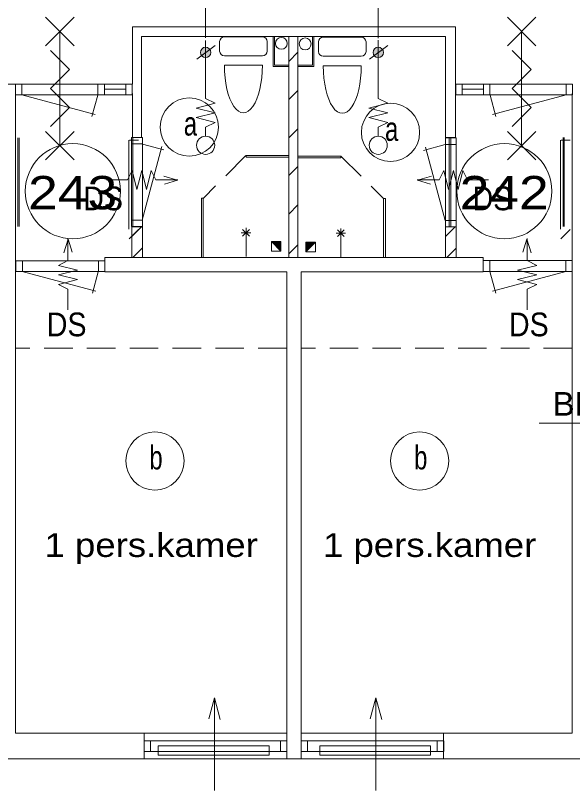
# Model space of a CAD drawing. Extents: x 295824 to 414724, y 24924 to 109024.
# Drawn here: x 320086 to 325944, y 87221 to 95369 of the extents above; entities that cross this region are included whole.
import ezdxf
from ezdxf.enums import TextEntityAlignment as Align

# ---------------------------------------------------------------- set-up
doc = ezdxf.new("R2010")
doc.units = 0
doc.header["$LTSCALE"] = 100
doc.linetypes.add('MEDIUM_DASHED', pattern=[4.5, 3, -1.5])
for name, color, linetype, lineweight in [('1', 7, 'Continuous', 13), ('16', 7, 'Continuous', 13), ('24', 7, 'Continuous', 13), ('61', 7, 'Continuous', 13)]:
    doc.layers.add(name, color=color, linetype=linetype, lineweight=lineweight)

msp = doc.modelspace()

# ---------------------------------------------------------------- hatches: boundary and pattern name
at = {"layer": '24'}
for points in [[(322140.1, 94981.2, 1), (322031.5, 94981.2, 1)], [(323955.6, 94981.2, 1), (323847, 94981.2, 1)]]:
    msp.add_hatch(color=256, dxfattribs=at).paths.add_polyline_path(points)
at = {"layer": '61'}
for points in [[(322777.9, 92991.3), (322877.9, 92891.3), (322877.9, 92991.3)], [(323240.3, 92985.9), (323140.3, 92885.9), (323140.3, 92985.9)]]:
    msp.add_hatch(color=256, dxfattribs=at).paths.add_polyline_path(points)

# ---------------------------------------------------------------- linework, layer by layer
at = {"layer": '1'}
for p, q in [((322085.8, 95135.8), (322085.8, 96018.7)), ((323901.3, 95130.8), (323901.3, 96018.7))]:
    msp.add_line(p, q, dxfattribs=at)
at = {"layer": '16'}
for p, q in [((321413.1, 93739.9), (321363.1, 93539.9)), ((324690.6, 93739.9), (324740.6, 93539.9)), ((320536.7, 92641.7), (320736.7, 92591.7)), ((325567, 92641.7), (325367, 92591.7))]:
    msp.add_line(p, q, dxfattribs=at)
at = {"layer": '24'}
for p, q in [((322085.8, 94545.8), (322085.8, 95106.6)), ((323901.3, 94545.8), (323901.3, 95108.1)), ((321994.2, 94910.4), (322185.7, 95052.1)), ((323809.7, 94910.4), (324001.2, 95052.1)), ((321788.5, 93636.5), (321644.3, 93681.5)), ((321652.7, 93594.1), (321788.5, 93636.5)), ((324315.2, 93636.5), (324459.3, 93681.5)), ((324451, 93594.1), (324315.2, 93636.5)), ((320640.1, 93017.1), (320595, 92872.9)), ((320682.5, 92881.3), (320640.1, 93017.1)), ((325421.2, 92881.3), (325463.6, 93017.1)), ((325463.6, 93017.1), (325508.6, 92872.9)), ((325591.5, 91082.6), (327952.3, 91082.6)), ((322177.4, 88195.7), (322117.8, 87973.2)), ((323876.3, 88195.7), (323816.7, 87973.2))]:
    msp.add_line(p, q, dxfattribs=at)
for points in [[(322085.8, 94095.8), (322085.8, 94195.8), (322185.8, 94245.8), (321985.8, 94295.8), (322185.8, 94345.8), (321985.8, 94395.8), (322185.8, 94445.8), (322085.8, 94495.8), (322085.8, 94545.8)], [(323901.3, 94095.8), (323901.3, 94195.8), (324001.3, 94245.8), (323801.3, 94295.8), (324001.3, 94345.8), (323801.3, 94395.8), (324001.3, 94445.8), (323901.3, 94495.8), (323901.3, 94545.8)], [(321363.1, 93539.9), (321313.1, 93739.9), (321263.1, 93639.9), (321044.4, 93639.9)], [(321794.4, 93639.9), (321563.1, 93639.9), (321513.1, 93739.9), (321463.1, 93539.9), (321413.1, 93739.9)], [(324309.3, 93639.9), (324540.6, 93639.9), (324590.6, 93739.9), (324640.6, 93539.9), (324690.6, 93739.9)], [(324740.6, 93539.9), (324790.6, 93739.9), (324840.6, 93639.9), (325059.3, 93639.9)], [(320636.7, 93023), (320636.7, 92791.7), (320536.7, 92741.7), (320736.7, 92691.7), (320536.7, 92641.7)], [(325467, 93023), (325467, 92791.7), (325567, 92741.7), (325367, 92691.7), (325567, 92641.7)], [(320736.7, 92591.7), (320536.7, 92541.7), (320636.7, 92491.7), (320636.7, 92273)], [(325367, 92591.7), (325567, 92541.7), (325467, 92491.7), (325467, 92273)], [(322177.4, 87220.7), (322177.4, 88195.7), (322239.1, 87965.5)], [(323876.3, 87220.7), (323876.3, 88195.7), (323938, 87965.5)]]:
    msp.add_lwpolyline(points, dxfattribs=at)
for points in [[(321586.1, 87691.5), (322752, 87691.5), (322752, 87591.5), (321586.1, 87591.5)], [(323285, 87691.5), (324451, 87691.5), (324451, 87591.5), (323285, 87591.5)]]:
    msp.add_lwpolyline(points, close=True, dxfattribs=at)
for centre, radius in [((322085.8, 94981.2), 54.3), ((323901.3, 94981.2), 54.3), ((322085.8, 94004.2), 95), ((323901.3, 94004.2), 95)]:
    msp.add_circle(centre, radius, dxfattribs=at)
at = {"layer": '61'}
for p, q in [((320403, 95051.1), (320703, 95351.1)), ((320703, 95051.1), (320403, 95351.1)), ((325258.8, 95051.1), (325558.8, 95351.1)), ((325558.8, 95051.1), (325258.8, 95351.1)), ((320553, 95201.1), (320553, 94001.1)), ((325408.8, 95201.1), (325408.8, 94001.1)), ((321409.7, 94086.3), (321409.7, 95148.4)), ((322232.9, 94995.4), (322232.9, 95095.4)), ((322282.9, 95145.4), (322682.9, 95145.4)), ((322732.9, 95095.4), (322732.9, 94995.4)), ((322794.7, 94833.4), (322794.7, 95148.4)), ((322809.7, 94848.4), (322809.7, 95148.4)), ((322959.7, 92823.4), (322959.7, 95148.4)), ((323056, 92823.4), (323056, 95148.4)), ((323209.8, 95147.9), (323209.8, 94847.9)), ((323322.2, 95140.5), (323722.2, 95140.5)), ((323272.2, 94990.5), (323272.2, 95090.5)), ((323772.2, 95090.5), (323772.2, 94990.5)), ((322682.9, 94945.4), (322282.9, 94945.4)), ((323055.4, 94982.4), (322959.6, 94886.7)), ((323722.2, 94940.5), (323322.2, 94940.5)), ((322959.7, 94848.4), (322809.7, 94848.4)), ((323209.8, 94847.9), (323059.8, 94847.9)), ((322282.9, 94845.4), (322682.9, 94845.4)), ((322959.7, 94833.4), (322794.7, 94833.4)), ((323322.2, 94840.5), (323722.2, 94840.5)), ((319949.3, 94648.3), (320090.5, 94648.3)), ((320153.5, 94648.3), (320153.5, 94534.3)), ((320953.5, 94648.3), (320953.5, 94534.3)), ((321020.5, 94648.3), (321020.5, 94534.3)), ((321246.5, 94648.3), (321246.5, 94534.3)), ((324714.9, 94084.9), (324714.9, 94650.7)), ((324783.1, 94648.3), (324783.1, 94534.3)), ((325009.1, 94648.3), (325009.1, 94534.3)), ((325076.1, 94648.3), (325076.1, 94534.3)), ((325876.1, 94648.3), (325876.1, 94534.3)), ((320087.1, 94548.4), (320087.1, 87823.4)), ((320152.7, 94533.7), (320925.4, 94326.6)), ((320951.1, 94533.1), (320890.3, 94306.2)), ((321246.5, 94594.2), (321020.5, 94594.2)), ((321314.9, 94086.3), (321314.9, 94548.4)), ((323055.4, 94581.5), (322959.6, 94485.8)), ((324783.1, 94594.2), (325009.1, 94594.2)), ((325078.4, 94533.1), (325139.2, 94306.2)), ((325876.9, 94533.7), (325104.1, 94326.6)), ((325940.1, 94548.4), (325940.1, 87823.4)), ((320403, 93851.1), (320703, 94151.1)), ((320703, 93851.1), (320403, 94151.1)), ((323055.4, 94178.2), (322959.6, 94082.4)), ((325258.8, 93851.1), (325558.8, 94151.1)), ((325558.8, 93851.1), (325258.8, 94151.1)), ((320110.3, 93148.9), (320110.3, 94081.3)), ((320126.1, 93148.9), (320126.1, 94081.3)), ((321278.6, 93123.7), (321278.6, 94057.7)), ((321380.8, 94058.5), (321286.1, 94058.5)), ((321307.4, 93151.5), (321307.4, 94085.5)), ((321409.7, 94086.3), (321314.9, 94086.3)), ((321318.4, 93151.5), (321318.4, 94085.5)), ((324714.9, 94084.9), (324609.7, 94084.9)), ((324648.4, 93148.9), (324648.4, 94081.3)), ((324664.2, 93148.9), (324664.2, 94081.3)), ((324720.9, 93148.9), (324720.9, 94081.3)), ((325816.7, 93123.7), (325816.7, 94057.7)), ((325918.9, 94058.5), (325824.2, 94058.5)), ((325845.5, 93151.5), (325845.5, 94085.5)), ((325856.5, 93151.5), (325856.5, 94085.5)), ((321307.4, 94018.5), (321421.4, 94018.5)), ((321419.5, 93217.8), (321626.5, 93990.5)), ((321420.1, 94016.2), (321646.9, 93955.4)), ((324603.1, 94011.9), (324376.2, 93951.2)), ((324603.7, 93213.5), (324396.6, 93986.3)), ((324720.9, 94014.3), (324606.9, 94014.3)), ((322960.8, 93897), (322511.3, 93897)), ((322511.3, 93897), (322511.3, 93879)), ((322960.4, 93879), (322511.3, 93879)), ((323057.5, 93891.6), (323506.9, 93891.6)), ((323057.8, 93873.6), (323506.9, 93873.6)), ((323506.9, 93891.6), (323506.9, 93873.6)), ((323055.4, 93782.2), (322959.6, 93686.4)), ((322060.4, 92829), (322060.4, 93449.5)), ((323957.8, 92823.6), (323957.8, 93444.1)), ((323055.4, 93377.6), (322959.6, 93281.8)), ((321307.4, 93218.5), (321421.4, 93218.5)), ((321420.8, 93151.5), (321306.8, 93151.5)), ((321420.1, 93148), (321310.1, 93148)), ((321310.1, 93148), (321310.1, 92823.9)), ((321409.8, 93146.8), (321310.1, 93047.1)), ((321420.1, 93148), (321420.1, 92823.9)), ((324720.9, 93214.3), (324606.9, 93214.3)), ((324708.3, 93146.8), (324608.6, 93047.1)), ((324719.1, 93148), (324609.1, 93148)), ((324609.1, 93148), (324609.1, 92823.9)), ((324719.1, 93148), (324719.1, 92823.9)), ((321381, 93118.9), (321281.3, 93019.2)), ((322560.3, 93085.5), (322460.3, 93085.5)), ((322545.6, 93050.1), (322474.9, 93120.8)), ((322545.6, 93120.8), (322474.9, 93050.1)), ((322510.3, 93035.5), (322510.3, 93135.5)), ((323458, 93080.1), (323558, 93080.1)), ((323472.6, 93044.8), (323543.3, 93115.5)), ((323472.6, 93115.5), (323543.3, 93044.8)), ((323508, 93030.1), (323508, 93130.1)), ((325919.1, 93118.9), (325819.4, 93019.2)), ((322510.3, 93035.5), (322510.3, 92835.5)), ((323508, 93030.1), (323508, 92830.1)), ((321418.4, 92924.2), (321318.7, 92824.5)), ((323055.4, 92959.5), (322959.6, 92863.7)), ((324720.5, 92924.2), (324620.9, 92824.5)), ((321420.1, 92823.9), (321310.1, 92823.9)), ((324719.1, 92823.9), (324609.1, 92823.9)), ((320158, 92790.9), (320158, 92676.9)), ((320958, 92790.9), (320958, 92676.9)), ((321025, 92790.9), (321025, 92676.9)), ((325005.7, 92791.9), (325005.7, 92677.9)), ((325072.7, 92791.9), (325072.7, 92677.9)), ((325872.7, 92791.9), (325872.7, 92677.9)), ((320157.3, 92676.2), (320930, 92469.2)), ((320955.7, 92675.6), (320894.9, 92448.8)), ((322940.1, 87553.4), (322940.1, 92673.4)), ((323090.1, 87553.4), (323090.1, 92673.4)), ((325075.1, 92676.7), (325135.8, 92449.8)), ((325873.5, 92677.3), (325100.7, 92470.3)), ((320087.1, 87823.4), (322940.1, 87823.4)), ((321440.7, 87552.2), (321440.7, 87822.2)), ((325940.1, 87823.4), (323090.1, 87823.4)), ((324588.7, 87552.2), (324588.7, 87822.4)), ((321507.5, 87630.5), (321507.5, 87744.3)), ((322872.5, 87629.9), (322872.5, 87743.9)), ((323156, 87630.8), (323156, 87744.8)), ((324520.3, 87630.5), (324520.3, 87744.2)), ((326233, 87553.4), (307806, 87553.4))]:
    msp.add_line(p, q, dxfattribs=at)
at = {"layer": '61', "linetype": 'MEDIUM_DASHED'}
for p, q in [((322509.2, 93896.5), (322062.4, 93449.6)), ((323509, 93891.2), (323955.9, 93444.3)), ((322937.9, 91870), (320090.8, 91870)), ((325940.1, 91870), (323091.2, 91870))]:
    msp.add_line(p, q, dxfattribs=at)
at = {"layer": '61'}
for points in [[(324714.9, 94648.4), (324714.9, 95248.4), (321314.9, 95248.4), (321314.9, 94648.4)], [(324609.7, 94084.9), (324609.7, 95148.4), (321409.7, 95148.4)], [(323224.8, 95147.9), (323224.8, 94832.9), (323059.8, 94832.9)], [(320453, 95001.1), (320653, 94801.1), (320453, 94601.1), (320653, 94401.1), (320453, 94201.1)], [(325308.8, 95001.1), (325508.8, 94801.1), (325308.8, 94601.1), (325508.8, 94401.1), (325308.8, 94201.1)], [(322042.4, 92829), (322042.4, 93449.5), (322060.4, 93449.5)], [(323975.8, 92823.6), (323975.8, 93444.1), (323957.8, 93444.1)], [(322877.9, 92891.3), (322877.9, 92991.3), (322777.9, 92991.3)], [(323140.3, 92885.9), (323140.3, 92985.9), (323240.3, 92985.9)], [(323089.9, 92673.4), (325004.9, 92673.4), (325004.9, 92823.4), (321025.5, 92823.4)], [(322939.9, 92673.4), (321025.5, 92673.4), (321025.5, 92823.4)], [(320091, 92790.9), (320091, 92676.9), (321025, 92676.9)], [(321025, 92790.9), (320091, 92790.9), (320091, 92676.9)], [(325939.7, 92791.9), (325939.7, 92677.9), (325005.7, 92677.9)], [(325005.7, 92791.9), (325939.7, 92791.9), (325939.7, 92677.9)]]:
    msp.add_lwpolyline(points, dxfattribs=at)
for points in [[(321313.5, 94648.3), (321313.5, 94534.3), (320086.5, 94534.3), (320086.5, 94648.3)], [(321313.5, 94648.3), (321313.5, 94534.3), (320086.5, 94534.3), (320086.5, 94648.3)], [(325943.1, 94648.3), (325943.1, 94534.3), (324716.7, 94534.3), (324716.7, 94648.3)], [(325943.1, 94648.3), (325943.1, 94534.3), (324716.7, 94534.3), (324716.7, 94648.3)], [(321307.4, 93151.5), (321307.4, 94085.5), (321421.4, 94085.5), (321421.4, 93151.5)], [(324720.9, 94082.2), (324606.9, 94082.2), (324606.9, 93148.2), (324720.9, 93148.2)], [(322877.9, 92891.3), (322777.9, 92891.3), (322777.9, 92991.3)], [(322777.9, 92991.3), (322877.9, 92891.3), (322877.9, 92991.3)], [(323140.3, 92885.9), (323240.3, 92885.9), (323240.3, 92985.9)], [(323240.3, 92985.9), (323140.3, 92885.9), (323140.3, 92985.9)], [(321440.6, 87630.3), (321440.6, 87744.3), (322939.3, 87744.3), (322939.3, 87630.3)], [(323089.6, 87630.5), (323089.6, 87744.5), (324589, 87744.5), (324589, 87630.5)]]:
    msp.add_lwpolyline(points, close=True, dxfattribs=at)
for centre, radius in [((322882.2, 95075.9), 62.5), ((323132.2, 95070.4), 62.5), ((321914.1, 94195.9), 306.3), ((324030, 94140.2), 306.3), ((320688.9, 93521.8), 500), ((325227, 93521.8), 500), ((321552.2, 90685.4), 306.3), ((324336.3, 90685.4), 306.3)]:
    msp.add_circle(centre, radius, dxfattribs=at)
for centre, start, end in [((322282.9, 95095.4), 90, 180), ((322682.9, 95095.4), 0, 90), ((323322.2, 95090.5), 90, 180), ((323722.2, 95090.5), 0, 90), ((322282.9, 94995.4), 180, 270), ((322682.9, 94995.4), 270, 0), ((323322.2, 94990.5), 180, 270), ((323722.2, 94990.5), 270, 0)]:
    msp.add_arc(centre, 50, start, end, dxfattribs=at)
for centre in [(322482.9, 94845.4), (323522.2, 94840.5)]:
    msp.add_ellipse(centre, major_axis=(0, -500), ratio=0.4, start_param=4.712389, end_param=7.853982, dxfattribs=at)

# ---------------------------------------------------------------- texts
at = {"layer": '24'}
for s, width, p in [('DS', 0.9, (320797.9, 93320.9)), ('DS', 0.9, (324892.4, 93320.9)), ('DS', 0.9, (320414.9, 91995.9)), ('DS', 0.9, (325275.5, 91995.9)), ('BESTAAND', 1.05, (325732.7, 91160.9))]:
    msp.add_text(s, height=250, dxfattribs=dict(at, width=width)).set_placement(p)
at = {"layer": '61'}
for s, width, p in [('a', 0.75, (321856.1, 94106.8)), ('a', 0.75, (323972, 94051)), ('b', 0.75, (321494.2, 90596.2)), ('b', 0.75, (324278.3, 90596.2)), ('1 pers.kamer', 1.15, (320390.9, 89676.2)), ('1 pers.kamer', 1.15, (323319.8, 89676.2))]:
    msp.add_text(s, height=250, dxfattribs=dict(at, width=width)).set_placement(p)
at = {"layer": '61', "width": 1.2}
for s, p in [('243', (320687.4, 93331.9)), ('242', (325225.5, 93331.9))]:
    msp.add_text(s, height=350, dxfattribs=at).set_placement(p, align=Align.CENTER)

doc.saveas('drawing.dxf')
